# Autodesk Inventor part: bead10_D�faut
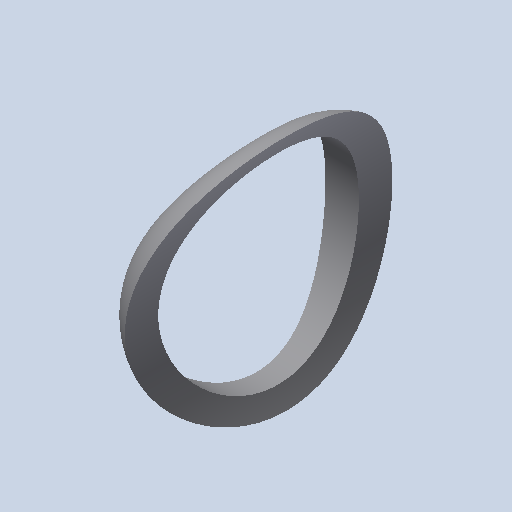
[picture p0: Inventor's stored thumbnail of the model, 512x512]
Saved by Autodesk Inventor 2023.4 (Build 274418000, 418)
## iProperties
Created: 2011-01
Part Number: bead10_D�faut
Document SubType Name: Modeling
Designer: eric
Density: 1 g/cm^3
Mass: 0.0717017 g
Surface Area: 2.42642 cm^2
Volume: 0.0717017 cm^3
Material: Générique
Appearance: Par défaut
Author: eric
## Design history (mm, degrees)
feature "Base1"
node "Corps solides"
node "Corps surfaciques"
node "Solide1"
